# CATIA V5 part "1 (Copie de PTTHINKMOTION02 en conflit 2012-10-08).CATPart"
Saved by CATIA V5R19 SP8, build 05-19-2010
Part number: 1
Bounding box of the stored display mesh (mm): x -230 to 10, y -16 to 6, z -24.997 to 24.997
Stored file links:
  E:\IAO_2010\iao\IAO_MMS_Groupe2\IAO_MMS_Groupe2\melguidj\Catia\1.CATPart
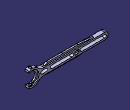
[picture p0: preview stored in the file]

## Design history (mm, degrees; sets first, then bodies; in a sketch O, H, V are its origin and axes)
Parameters
  AE1 = 180 mm
  AD1 = 70 mm
Body1 (main body)
  Sketch1 on zx-plane, origin (0, 0, 0), H (-1, 0, 0), V (0, 0, 1)
    line L1 (35.7071, -10) -> (220, -10)
    line L2 (220, 10) -> (35.7071, 10)
    point P1 (220, -10)
    point P2 (220, 10)
    construction line L3 (150, 0) -> (220, 0)
    point P3 (150, 0)
    line L4 (150, 5) -> (220, 5)
    line L5 (220, -5) -> (150, -5)
    arc A1 centre (220, 0) radius 5 from (220, 5) to (220, -5) cw
    arc A2 centre (150, 0) radius 5 from (150, -5) to (150, 5) cw
    construction line L6 (60, 0) -> (120, 0)
    point P9 (60, 0)
    point P10 (120, 0)
    line L7 (60, 5) -> (120, 5)
    line L8 (120, -5) -> (60, -5)
    arc A3 centre (120, 0) radius 5 from (120, 5) to (120, -5) cw
    arc A4 centre (60, 0) radius 5 from (60, -5) to (60, 5) cw
    arc A5 centre (0, 0) radius 20 from (-10, 17.3205) to (-10, -17.3205) cw
    point P15 (0, 0)
    line L9 (-10, 17.3205) -> (-10, 22.9129)
    point P18 (-10, 22.9129)
    line L10 (-10, -17.3205) -> (-10, -22.9129)
    arc A6 centre (0, 0) radius 25 from (-10, 22.9129) to (17.8536, 17.5) cw
    point P20 (0, 0)
    point P21 (-10, 22.9129)
    point P22 (22.9129, -10)
    arc A7 centre (0, 0) radius 25 from (17.8536, -17.5) to (-10, -22.9129) cw
    construction line L11 (20, 36.6166) -> (20, -39.7535)
    arc A8 centre (220, 0) radius 10 from (220, 10) to (220, -10) cw
    point P25 (220, 0)
    axis line L12 (-10, 39.084) -> (-10, -27.4612)
    reference projected point E1 (0, 0) from Sketch6
    arc A9 centre (35.7071, 35) radius 25 from (17.8536, 17.5) to (35.7071, 10) ccw
    arc A10 centre (35.7071, -35) radius 25 from (17.8536, -17.5) to (35.7071, -10) cw
    distance L3 L4 = 5
    distance L3 L1 = 10
    length L5 = 70
    distance L6 L7 = 5
    length L7 = 60
    distance P10 P3 = 30
    distance L11 A5 = 0
    radius A5 = 20
    distance P1 P2 = 20
    distance A1 A8 = 5
    distance L12 V = 10
    distance L9 P25 = 230
    radius A6 = 25
    radius A9 = 25
    radius A10 = 25
    horizontal: L1 H, L2 H, L3 H, L6 H
    tangency: A1 L4, A2 L4, A1 L5, A2 L5, A3 L7, A4 L7, A3 L8, A4 L8, A8 L1, A8 L2, A9 A6, A9 L2, A10 A7, A10 L1
    coincidence: P9 L3, P15 L6, P21 P18, P20 P15, A6 P22, A6 A7, L6 H, L9 L12, L10 L9, A7 P22, L1 P22
    vertical: L9 V, L10 V, L11 V, L12 V
    concentricity: A5 E1
  Pad1: profile Sketch1, direction (0, 1, 0), length 6, mirrored extent
  Sketch2 on xy-plane, origin (0, 0, 0), H (1, 0, 0), V (0, 1, 0)
    circle A1 centre (0, 0) radius 4
    point P1 (0, 0)
    radius A1 = 4
    coincidence: P1 O
  Pocket1: profile Sketch2, direction (0, 0, -1), through (limit type 3), opposite side through (limit type 3)
  Sketch3 on start face of Pad1, origin (0, -6, 0), H (1, 0, 0), V (0, 0, 1)
    circle A1 centre (-29, 0) radius 4
    point P1 (-29, 0)
    reference projected arc E1 centre (0, 0) radius 20 from (10, 17.3205) to (10, -17.3205) ccw from edge [start face of Pad1 | face of Pad1 from Sketch1.A5]
    radius A1 = 4
    distance A1 E1 = 5
    coincidence: P1 H
  Pad2: profile Sketch3, direction (0, -1, 0), length 10
  Sketch4 on zx-plane, origin (0, 0, 0), H (-1, 0, 0), V (0, 0, 1)
    arc A1 centre (0, 0) radius 15 from (6, -13.7477) to (6, 13.7477) ccw
    point P1 (6, -13.7477)
    point P2 (6, 13.7477)
    construction line L1 (6, 36.7811) -> (6, -37.0173)
    reference projected arc E1 centre (0, 0) radius 20 from (-10, -17.3205) to (-10, 17.3205) ccw from edge [face of Pad1 from Sketch1.A5 | end face of Pad1]
    arc A2 centre (0, 0) radius 20 from (6, -19.0788) to (6, 19.0788) ccw
    point P5 (6, 19.0788)
    point P6 (6, -19.0788)
    reference projected arc E2 centre (0, 0) radius 20 from (-10, -17.3205) to (-10, 17.3205) ccw from edge [face of Pad1 from Sketch1.A5 | end face of Pad1]
    line L2 (6, -19.0788) -> (6, -13.7477)
    line L3 (6, 13.7477) -> (6, 19.0788)
    construction line L4 (232.1602, 0) -> (-35.1645, 0)
    point P7 (232.1602, 0)
    point P9 (41, 10)
    line L5 (41, 10) -> (49.6603, 15)
    point P10 (49.6603, 15)
    line L6 (49.6603, 15) -> (96, 15)
    line L7 (96, 10) -> (41, 10)
    reference projected line E3 (220, 10) -> (35.7071, 10) from edge [face of Pad1 from Sketch1.L2 | end face of Pad1]
    point P11 (49.6603, 15)
    point P12 (49.6603, 15)
    axis line L8 (96, 56.5793) -> (96, -31.7607)
    point P15 (96, 15)
    point P16 (96, 10)
    point P17 (96, 15)
    point P18 (96, 10)
    point P19 (189.9116, 10)
    point P20 (142.3397, 15)
    point P21 (142.3397, 15)
    point P22 (142.3397, 15)
    point P23 (96, 15)
    point P24 (96, 10)
    point P25 (96, 15)
    point P26 (96, 10)
    line L9 (189.9116, 10) -> (142.3397, 15)
    line L10 (142.3397, 15) -> (96, 15)
    line L11 (96, 10) -> (189.9116, 10)
    point P27 (41, -10)
    point P28 (49.6603, -15)
    point P29 (49.6603, -15)
    point P30 (49.6603, -15)
    point P31 (96, -15)
    point P32 (96, -10)
    point P33 (96, -15)
    point P34 (96, -10)
    point P35 (189.9116, -10)
    point P36 (142.3397, -15)
    point P37 (142.3397, -15)
    point P38 (142.3397, -15)
    point P39 (96, -15)
    point P40 (96, -10)
    point P41 (96, -15)
    point P42 (96, -10)
    line L12 (41, -10) -> (49.6603, -15)
    line L13 (49.6603, -15) -> (96, -15)
    line L14 (96, -10) -> (41, -10)
    line L15 (189.9116, -10) -> (142.3397, -15)
    line L16 (142.3397, -15) -> (96, -15)
    line L17 (96, -10) -> (189.9116, -10)
    reference projected line E4 (220, 10) -> (35.7071, 10) from edge [face of Pad1 from Sketch1.L2 | end face of Pad1]
    distance L1 V = 6
    radius A1 = 15
    distance L6 L7 = 5
    angle L5 L7 = 30
    distance P9 L1 = 35
    distance L8 P9 = 55
    angle L11 L9 = 6
    vertical: L1 V, L2 V, L3 V, L8 V
    coincidence: L1 P2, P1 L1, P5 L1, P6 L1, A2 E2, P7 H, L7 E3, L6 P12, L5 P10, L8 P15, L8 P16, P11 P10, P16 P24, P15 P23, P20 P21, P28 P29, P31 P39, P32 P40, P36 P37, L11 E4
    concentricity: A1 E1
    horizontal: L6 H, L7 H
    symmetry: P10 P20 L8, P11 P21 L8, P15 P23 L8, P16 P24 L8, P9 P27 L4, P10 P28 L4, P11 P29 L4, P12 P30 L4, P15 P31 L4, P16 P32 L4, P17 P33 L4, P18 P34 L4, P19 P35 L4, P20 P36 L4, P21 P37 L4, P22 P38 L4, P23 P39 L4, P24 P40 L4, P25 P41 L4, P26 P42 L4, L5 L12 L4, L6 L13 L4, L7 L14 L4, L9 L15 L4, L10 L16 L4, L11 L17 L4
  Pad3: profile Sketch4, direction (0, 1, 0), length 2.5, mirrored extent
  Fillet1: radius 2, on edge [face of Pad3 from Sketch4.L3 | face of Pad1 from Sketch1.A5]
  Fillet2: radius 2, on edge [face of Pad1 from Sketch1.A5 | face of Pad3 from Sketch4.L2]
  Fillet3: radius 3, on edge [face of Pad1 from Sketch1.L2 | face of Pad3 from Sketch4.L5]; edge [face of Pad3 from Sketch4.L5 | face of Pad3 from Sketch4.L6]
  Fillet4: radius 3, on edge [face of Pad3 from Sketch4.L9 | face of Pad1 from Sketch1.L2]; edge [face of Pad3 from Sketch4.L10 | face of Pad3 from Sketch4.L9]; edge [face of Pad1 from Sketch1.L1 | face of Pad3 from Sketch4.L15]; edge [face of Pad3 from Sketch4.L15 | face of Pad3 from Sketch4.L16]; edge [face of Pad3 from Sketch4.L13 | face of Pad3 from Sketch4.L12]; edge [face of Pad3 from Sketch4.L12 | face of Pad1 from Sketch1.L1]
  Fillet5: radius 4, on edge [face of Pad3 from Sketch4.L2 | face of Pad3 from Sketch4.A1]; edge [face of Pad3 from Sketch4.A1 | face of Pad3 from Sketch4.L3]
  Sketch5 on end face of Pad1, origin (0, 6, 0), H (-1, 0, 0), V (0, 0, 1)
    construction line L1 (253.4328, 0) -> (-63.0915, 0)
    point P1 (253.4328, 0)
    spline S1 through (24.0575, 0) (31.4268, 4.5069) (47.5777, 0)
    point P3 (129, 5)
    line L2 (131, 5) -> (139, 5)
    line L3 (141, 3) -> (141, 0)
    line L4 (129, 0) -> (129, 3)
    point P4 (141, 5)
    point P5 (141, 0)
    point P6 (129, 0)
    reference projected line E1 (120, 5) -> (60, 5) from edge [end face of Pad1 | face of Pad1 from Sketch1.L7]
    spline S2 through (24.0575, 0) (31.4268, -4.5069) (47.5777, 0)
    point P7 (129, -5)
    point P8 (129, 0)
    line L5 (129, 0) -> (129, -3)
    point P9 (141, -5)
    line L6 (131, -5) -> (139, -5)
    point P10 (141, 0)
    line L7 (141, -3) -> (141, 0)
    axis line L8 (135, 24.944) -> (135, -24.0978)
    reference projected point E2 (150, 0) from axis of face of Pad1 from Sketch1.A2
    arc A1 centre (131, 3) radius 2 from (129, 3) to (131, 5) cw
    arc A2 centre (139, 3) radius 2 from (139, 5) to (141, 3) cw
    arc A3 centre (139, -3) radius 2 from (139, -5) to (141, -3) ccw
    arc A4 centre (131, -3) radius 2 from (131, -5) to (129, -3) cw
    point P25 (24.0575, 0)
    point P26 (47.5777, 0)
    point P27 (47.5777, 0)
    point P28 (24.0575, 0)
    point P29 (31.4268, 4.5069)
    point P30 (31.4268, -4.5069)
    distance L2 E1 = 0
    distance L8 E2 = 15
    distance L3 L8 = 6
    distance L4 L8 = 6
    radius A1 = 2
    radius A2 = 2
    radius A3 = 2
    radius A4 = 2
    coincidence: P1 H, P25 L1, P26 L1, P5 L1, P25 P28, P26 P27, P5 P10, P6 P8, L4 P3, L2 P3, L2 P4, L3 P4, L6 P9, L7 P9, L6 P7, L5 P7
    horizontal: L1 H, L2 H
    vertical: L3 V, L4 V, L8 V
    symmetry: S1 S2 L1, P3 P7 L1, P6 P8 L1, L4 L5 L1, P4 P9 L1, L2 L6 L1, P5 P10 L1, L3 L7 L1, P26 P27 L1, P25 P28 L1, P29 P30 L1
    tangency: A1 L4, A1 L2, A2 L2, A2 L3, A3 L6, A3 L7, A4 L6, A4 L5
  Pocket2: profile Sketch5, direction (0, -1, 0), through (limit type 6)
  Sketch6, origin (7.4637, -11, -2.8797), H (-0.933, 0, 0.36), V (0.36, 0, 0.933), geometry linked from another document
